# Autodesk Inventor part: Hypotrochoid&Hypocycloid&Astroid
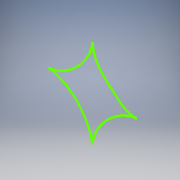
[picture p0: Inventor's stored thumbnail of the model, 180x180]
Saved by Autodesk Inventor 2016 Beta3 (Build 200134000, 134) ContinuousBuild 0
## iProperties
Created: 2008-02
Part Number: Hypotrochoid&Hypocycloid&Astroid
Document SubType Name: Modeling
Designer: Autodesk, Inc.
Density: 1 g/cm^3
Material: Generic
Appearance: Default
Author: Autodesk, Inc.
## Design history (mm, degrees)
sketch "Sketch1"
  geometry: 300 further points
  constraints: 300 other
